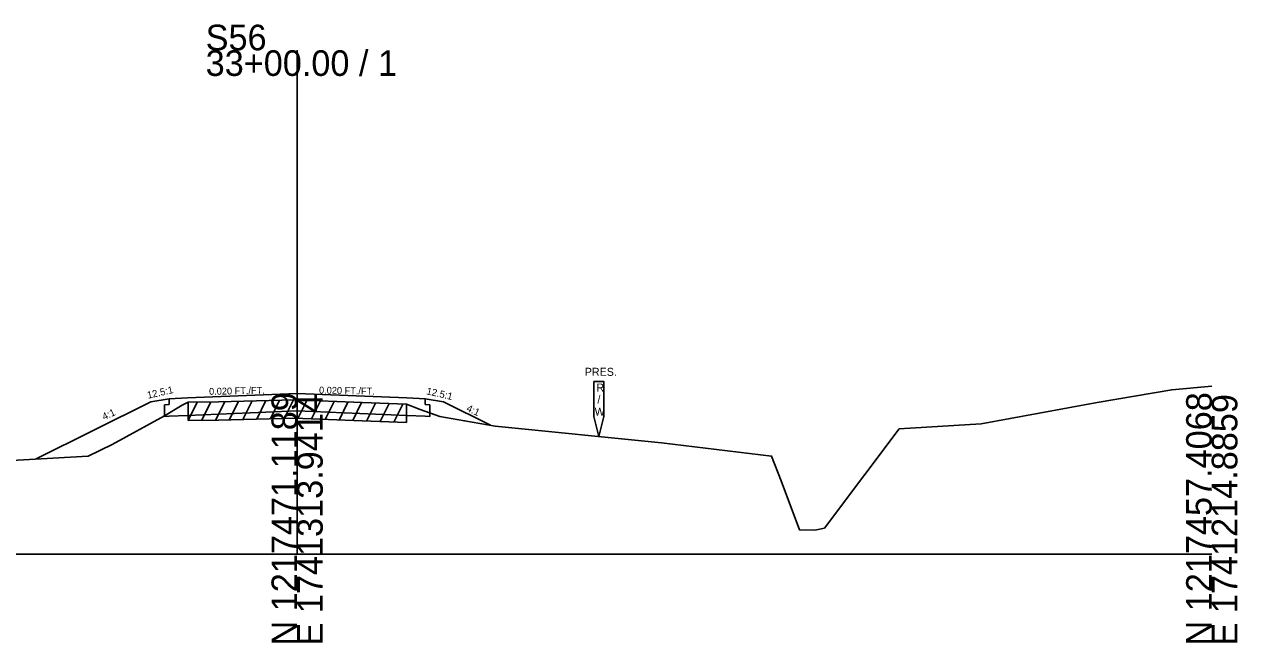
# Model space of a CAD drawing. Extents: x -26 to 1203, y -10 to 19541.
# Drawn here: x 70.2 to 202.8, y 7990.3 to 8057.9 of the extents above; entities that cross this region are included whole.
import ezdxf

# ---------------------------------------------------------------- set-up
doc = ezdxf.new("R2010")
doc.units = 0
for name, color, linetype in [('RD_GPK_XS_Cell', 7, 'Continuous'), ('RD_XS_Base', 7, 'Continuous'), ('RD_XS_EarthShd', 7, 'Continuous'), ('RD_XS_ExGround', 7, 'Continuous'), ('RD_XS_ExPaveRet', 7, 'Continuous'), ('RD_XS_ExRW', 7, 'Continuous'), ('RD_XS_Pave', 7, 'Continuous'), ('RD_XS_TX_Elev_EX', 7, 'Continuous'), ('RD_XS_TX_Slope', 7, 'Continuous')]:
    doc.layers.add(name, color=color, linetype=linetype)

msp = doc.modelspace()

# ---------------------------------------------------------------- linework, layer by layer
at = {"layer": 'RD_GPK_XS_Cell'}
for p, q in [((100, 8000), (100, 8055.06)), ((0, 8000), (100, 8000)), ((100, 8000), (200, 8000))]:
    msp.add_line(p, q, dxfattribs=at)
at = {"layer": 'RD_XS_Base'}
for p, q in [((86, 8016.34), (85.5, 8016.32)), ((85.5, 8015.05), (85.5, 8016.32)), ((86, 8016.34), (86, 8016.98)), ((114, 8016.34), (114, 8016.98)), ((114, 8016.34), (114.5, 8016.32)), ((114.5, 8015.05), (114.5, 8016.32)), ((86, 8015.07), (85.5, 8015.05)), ((86, 8015.07), (88, 8015.16)), ((88, 8015.16), (100, 8015.66)), ((112, 8015.16), (100, 8015.66)), ((114, 8015.07), (112, 8015.16)), ((114, 8015.07), (114.5, 8015.05))]:
    msp.add_line(p, q, dxfattribs=at)
at = {"layer": 'RD_XS_EarthShd'}
for p, q in [((84, 8016.65), (71.48, 8010.39)), ((86, 8016.98), (84, 8016.65)), ((114, 8016.98), (116, 8016.65)), ((116, 8016.65), (121.13, 8014.08))]:
    msp.add_line(p, q, dxfattribs=at)
at = {"layer": 'RD_XS_ExGround'}
msp.add_lwpolyline([(55.9, 8009.49), (77.17, 8010.71), (79.78, 8011.96), (85.5, 8015.12), (87.42, 8016.26), (88.08, 8016.6), (91.41, 8016.64), (99.73, 8016.85), (107.1, 8016.55), (111.97, 8016.38), (113.45, 8015.81), (115.59, 8015.02), (118.3, 8014.57), (121.65, 8013.99), (139.83, 8012.14), (151.88, 8010.71), (152.91, 8008.01), (154.93, 8002.63), (156.59, 8002.6), (157.65, 8002.83), (162.07, 8008.7), (165.84, 8013.67), (174.78, 8014.22), (187.48, 8016.56), (195.62, 8017.95), (200, 8018.35)], dxfattribs=at)
at = {"layer": 'RD_XS_ExPaveRet'}
for p, q in [((88.08, 8014.6), (89.08, 8016.61)), ((88.08, 8014.6), (88.08, 8016.6)), ((89.58, 8014.62), (90.58, 8016.63)), ((91.08, 8014.63), (92.09, 8016.65)), ((92.58, 8014.67), (93.59, 8016.69)), ((94.08, 8014.7), (95.09, 8016.73)), ((95.58, 8014.74), (96.59, 8016.77)), ((97.08, 8014.78), (98.09, 8016.81)), ((98.58, 8014.82), (99.59, 8016.84)), ((100.08, 8014.83), (101.05, 8016.79)), ((101.58, 8014.77), (102.55, 8016.73)), ((103.08, 8014.71), (104.05, 8016.67)), ((104.58, 8014.65), (105.55, 8016.61)), ((106.08, 8014.59), (107.05, 8016.55)), ((107.58, 8014.53), (108.56, 8016.5)), ((109.08, 8014.48), (110.06, 8016.45)), ((110.58, 8014.43), (111.56, 8016.4)), ((111.97, 8016.38), (111.97, 8014.38)), ((91.41, 8014.64), (99.73, 8014.85)), ((99.73, 8014.85), (107.1, 8014.55)), ((88.08, 8014.6), (91.41, 8014.64)), ((107.1, 8014.55), (111.97, 8014.38))]:
    msp.add_line(p, q, dxfattribs=at)
at = {"layer": 'RD_XS_ExRW'}
msp.add_lwpolyline([(132.45, 8018.85), (133.55, 8018.85), (133.55, 8015.02), (133, 8012.83), (132.45, 8015.02)], close=True, dxfattribs=at)
at = {"layer": 'RD_XS_Pave'}
for p, q in [((88, 8017.06), (100, 8017.56)), ((112, 8017.06), (100, 8017.56)), ((86, 8016.98), (88, 8017.06)), ((114, 8016.98), (112, 8017.06))]:
    msp.add_line(p, q, dxfattribs=at)

# ---------------------------------------------------------------- texts
at = {"layer": 'RD_GPK_XS_Cell'}
for s, p in [('S56', (90, 8055.06)), ('33+00.00 / 1', (90, 8052.26))]:
    msp.add_text(s, height=2.8, dxfattribs=at).set_placement(p)
for s, p in [('N 1217471.1189', (100, 7990)), ('E 1741313.9414', (102.8, 7990)), ('N 1217457.4068', (200, 7990)), ('E 1741214.8859', (202.8, 7990))]:
    msp.add_text(s, height=2.8, rotation=90, dxfattribs=at).set_placement(p)
at = {"layer": 'RD_XS_ExRW'}
for s, p in [('PRES.', (131.45, 8019.48)), ('R', (132.71, 8017.76)), ('/', (132.83, 8016.45)), ('W', (132.53, 8015.13))]:
    msp.add_text(s, height=0.875, dxfattribs=at).set_placement(p)
at = {"layer": 'RD_XS_TX_Elev_EX'}
msp.add_text('845.42', height=0.1, rotation=90, dxfattribs=at).set_placement((100.1, 8016.84))
at = {"layer": 'RD_XS_TX_Slope'}
for s, height, rotation, p in [('12.5:1', 0.778, 12.7511, (83.69, 8016.97)), ('0.020 FT./FT.', 0.7518, 1.1916, (90.38, 8017.4)), ('0.020 FT./FT.', 0.7518, 358.8084, (102.39, 8017.55)), ('12.5:1', 0.778, 347.2489, (114.09, 8017.47)), ('4:1', 0.778, 335.081, (118.44, 8015.67)), ('4:1', 0.778, 24.919, (78.9, 8014.61))]:
    msp.add_text(s, height=height, rotation=rotation, dxfattribs=at).set_placement(p)

doc.saveas('drawing.dxf')
